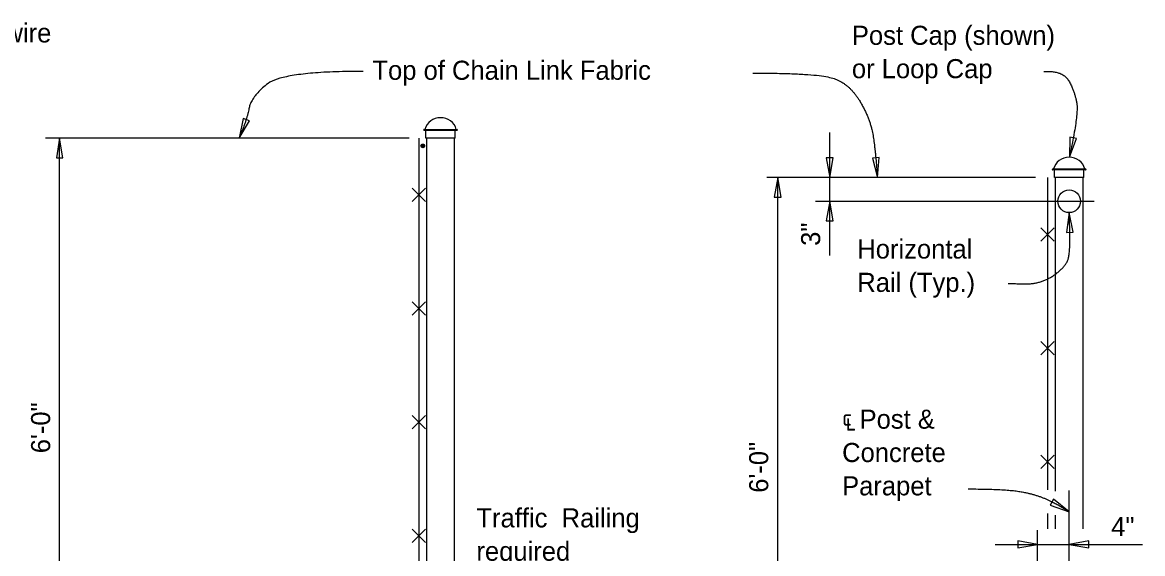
# Model space of a CAD drawing. Extents: x 0 to 41, y -96 to 25.
# Drawn here: x 29.01 to 40.83, y -77.25 to -71.64 of the extents above; entities that cross this region are included whole.
import ezdxf

# ---------------------------------------------------------------- set-up
doc = ezdxf.new("R2010")
doc.units = 0
for name, color, linetype in [('CL_Major', 7, 'Continuous'), ('Dimension', 7, 'Continuous'), ('Miscellaneous', 7, 'Continuous'), ('SteelMisc', 7, 'Continuous'), ('TextStructures', 7, 'Continuous')]:
    doc.layers.add(name, color=color, linetype=linetype)

msp = doc.modelspace()

# ---------------------------------------------------------------- linework, layer by layer
at = {"layer": 'CL_Major'}
for p, q in [((37.378, -73.53), (40.319, -73.53)), ((40.054, -80.805), (40.054, -76.585))]:
    msp.add_line(p, q, dxfattribs=at)
at = {"layer": 'Dimension'}
for p, q in [((33.092, -72.863), (29.256, -72.863)), ((29.406, -81.53), (29.406, -72.863)), ((37.528, -74.104), (37.528, -72.806)), ((39.699, -73.28), (36.866, -73.28)), ((36.98, -81.509), (36.98, -73.28)), ((39.72, -79.109), (39.72, -77.002)), ((39.274, -77.152), (40.828, -77.152))]:
    msp.add_line(p, q, dxfattribs=at)
for points in [[(31.3, -72.863), (31.408, -72.681), (31.342, -72.656)], [(29.406, -72.863), (29.371, -73.071), (29.441, -73.071)], [(40.057, -73.065), (40.131, -72.867), (40.062, -72.854)], [(37.528, -73.28), (37.563, -73.071), (37.492, -73.071)], [(38.031, -73.28), (38.049, -73.069), (37.979, -73.075)], [(36.98, -73.28), (36.944, -73.488), (37.015, -73.488)], [(37.528, -73.53), (37.492, -73.738), (37.563, -73.738)], [(40.054, -73.649), (40.024, -73.859), (40.095, -73.857)], [(40.054, -76.807), (39.889, -76.676), (39.855, -76.737)], [(39.72, -77.152), (39.512, -77.116), (39.512, -77.187)], [(40.054, -77.152), (40.262, -77.187), (40.262, -77.116)]]:
    msp.add_lwpolyline(points, close=True, dxfattribs=at)
for points in [[(32.608, -72.159), (31.76, -72.159), (31.424, -72.431), (31.383, -72.666), (31.3, -72.863)], [(36.717, -72.177), (37.4, -72.177), (37.736, -72.289), (37.958, -72.661), (38.014, -73.021), (38.031, -73.28)], [(39.786, -72.161), (39.992, -72.146), (40.118, -72.389), (40.152, -72.614), (40.057, -73.065)], [(39.41, -74.399), (39.436, -74.399), (39.754, -74.405), (40.017, -74.227), (40.072, -74.05), (40.054, -73.649)], [(38.988, -76.567), (39.396, -76.567), (39.727, -76.631), (39.975, -76.753), (40.054, -76.807)]]:
    msp.add_open_spline(points, degree=2, dxfattribs=at)
at = {"layer": 'Miscellaneous'}
for p, q in [((33.265, -73.392), (33.124, -73.534)), ((33.124, -73.392), (33.265, -73.534)), ((39.895, -73.809), (39.754, -73.95)), ((39.754, -73.809), (39.895, -73.95)), ((33.265, -74.592), (33.124, -74.734)), ((33.124, -74.592), (33.265, -74.734)), ((39.895, -75.009), (39.754, -75.15)), ((39.754, -75.009), (39.895, -75.15)), ((33.265, -75.792), (33.124, -75.934)), ((33.124, -75.792), (33.265, -75.934)), ((39.895, -76.209), (39.754, -76.35)), ((39.754, -76.209), (39.895, -76.35)), ((33.265, -76.992), (33.124, -77.134)), ((33.124, -76.992), (33.265, -77.134))]:
    msp.add_line(p, q, dxfattribs=at)
for points in [[(33.195, -72.863), (33.195, -78.863)], [(39.825, -73.28), (39.825, -76.577)], [(39.825, -76.825), (39.825, -76.988)]]:
    msp.add_lwpolyline(points, dxfattribs=at)
at = {"layer": 'SteelMisc'}
for p, q in [((33.251, -72.771), (33.596, -72.771)), ((33.195, -72.863), (33.195, -78.863)), ((33.596, -72.783), (33.251, -72.783)), ((33.27, -72.863), (33.27, -72.783)), ((33.578, -72.863), (33.27, -72.863)), ((33.278, -79.198), (33.278, -72.863)), ((33.57, -79.198), (33.57, -72.863)), ((33.578, -72.863), (33.578, -72.783)), ((39.881, -73.188), (40.226, -73.188)), ((40.226, -73.2), (39.881, -73.2)), ((39.9, -73.28), (39.9, -73.2)), ((40.208, -73.28), (40.208, -73.2)), ((40.208, -73.28), (39.9, -73.28)), ((39.908, -76.592), (39.908, -73.28)), ((40.2, -76.988), (40.2, -73.28)), ((39.908, -76.988), (39.908, -76.844))]:
    msp.add_line(p, q, dxfattribs=at)
for centre, radius in [((33.236, -72.946), 0.0197), ((33.236, -72.946), 0.0172), ((33.236, -72.946), 0.0147), ((33.236, -72.946), 0.0122), ((33.236, -72.946), 0.00975), ((33.236, -72.946), 0.00725), ((33.236, -72.946), 0.00475), ((33.236, -72.946), 0.00225), ((40.054, -73.53), 0.12)]:
    msp.add_circle(centre, radius, dxfattribs=at)
for centre, start, end in [((33.252, -72.777), 91.1647, 268.8353), ((33.596, -72.777), 271.1647, 88.8353), ((39.882, -73.194), 91.1647, 268.8353), ((40.226, -73.194), 271.1647, 88.8353)]:
    msp.add_arc(centre, 0.00613, start, end, dxfattribs=at)
for centre in [(33.424, -72.812), (40.054, -73.229)]:
    msp.add_ellipse(centre, major_axis=(0.171, 0), ratio=0.957868, start_param=0.252602, end_param=2.888574, dxfattribs=at)

# ---------------------------------------------------------------- texts
at = {"layer": 'Dimension'}
for s, p in [('No. 9 gage zinc coated tie wire ', (25.632, -71.854)), ('Post Cap (shown) ', (37.762, -71.879)), ('or Loop Cap', (37.762, -72.231)), ('Horizontal', (37.819, -74.135)), ('Rail (Typ.)', (37.819, -74.487)), ('℄ Post &', (37.659, -75.931)), ('Concrete', (37.659, -76.283)), ('Parapet', (37.659, -76.635)), ('Traffic  Railing', (33.802, -76.973)), ('required', (33.802, -77.325))]:
    msp.add_text(s, height=0.2016, dxfattribs=at).set_placement(p)
at = {"layer": 'TextStructures'}
for s, p in [('Top of Chain Link Fabric', (32.705, -72.248)), ('4"', (40.497, -77.065))]:
    msp.add_text(s, height=0.2016, dxfattribs=at).set_placement(p)
for s, p in [('3"', (37.428, -74.001)), ('6\'-0"', (29.306, -76.19)), ('6\'-0"', (36.88, -76.607))]:
    msp.add_text(s, height=0.2016, rotation=90, dxfattribs=at).set_placement(p)

doc.saveas('drawing.dxf')
